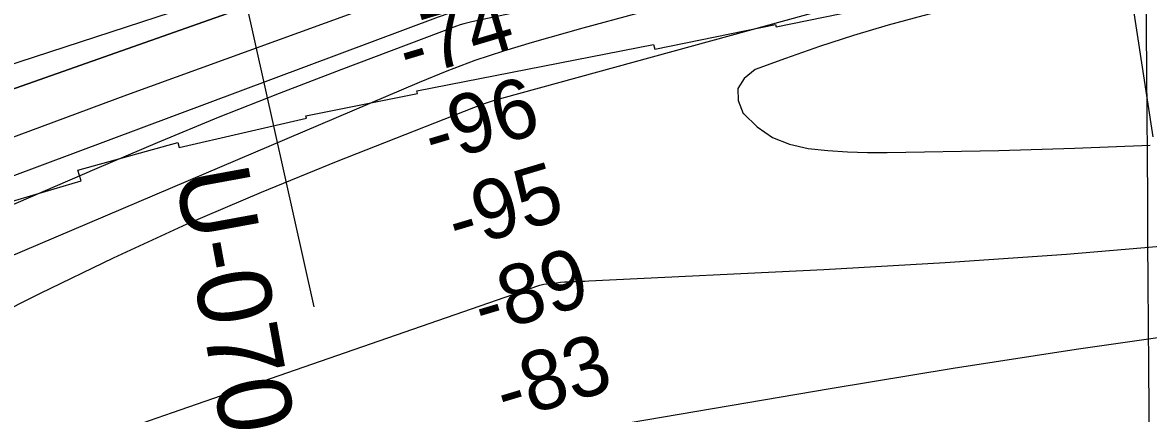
# Model space of a CAD drawing. Extents: x 3508733 to 3546731, y 546897 to 572481.
# Drawn here: x 3516840 to 3518107, y 565110 to 565549 of the extents above; entities that cross this region are included whole.
import ezdxf

# ---------------------------------------------------------------- set-up
doc = ezdxf.new("R2010")
doc.units = 0
for name, color, linetype in [('V-CHAN-NAID', 7, 'Continuous'), ('V-GRID-MAJR', 7, 'Continuous'), ('V-RIVR-RANG', 7, 'Continuous'), ('V-RIVR-RANG-IDEN', 7, 'Continuous'), ('V-RRAP-RVMT', 7, 'Continuous'), ('V-TOPO-DPTH', 7, 'Continuous'), ('V-TOPO-MAJR', 7, 'Continuous'), ('V-TOPO-MINR', 7, 'Continuous')]:
    doc.layers.add(name, color=color, linetype=linetype)

msp = doc.modelspace()

# ---------------------------------------------------------------- linework, layer by layer
at = {"layer": 'V-GRID-MAJR'}
msp.add_spline([(3518190.879, 552332.11), (3518151.221, 558391.11), (3518111.551, 564452.0430000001), (3518071.881, 570512.993), (3518071.8680000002, 570514.91)], degree=3, dxfattribs=at)
at = {"layer": 'V-RIVR-RANG'}
for p, q in [((3517971.68, 566330.2852), (3518111.514, 565420.9742)), ((3516975.6473, 566088.6846999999), (3517167.2507, 565229.797))]:
    msp.add_line(p, q, dxfattribs=at)
at = {"layer": 'V-RRAP-RVMT'}
msp.add_lwpolyline([(3516793.5560000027, 565338.3850000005), (3516905.4190000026, 565371.5210000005), (3516901.7340000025, 565383.6640000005), (3517014.2890000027, 565414.4800000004), (3517015.6620000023, 565408.8910000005), (3517159.1540000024, 565441.9540000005), (3517158.5010000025, 565444.4560000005), (3517284.1880000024, 565469.7160000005), (3517283.4300000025, 565472.6210000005), (3517549.7740000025, 565524.6950000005), (3517551.1010000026, 565519.6100000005), (3517687.0100000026, 565547.1750000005), (3517687.6420000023, 565544.7540000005), (3517830.8750000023, 565573.8730000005), (3517828.7590000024, 565584.6120000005), (3517965.9410000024, 565611.9040000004), (3517966.721000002, 565608.9180000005), (3518119.8880000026, 565637.1650000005)], dxfattribs=at)
at = {"layer": 'V-TOPO-DPTH'}
for points in [[(3518423.3886862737, 565898.4655466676), (3517326.2683833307, 565662.5643742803), (3517315.0726943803, 565659.9749688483), (3517303.9387676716, 565657.1565487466), (3517292.897484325, 565653.9946066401), (3517281.91796322, 565650.603649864), (3516680.8731781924, 565454.7229584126), (3516555.292542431, 565412.9760251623), (3516430.053385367, 565370.2471805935), (3516305.3264463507, 565326.0454690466), (3516180.9409860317, 565280.8618461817), (3515954.5417875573, 565197.1078883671)], [(3518423.3886862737, 565898.4655466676), (3517326.2683833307, 565662.5643742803), (3517315.0726943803, 565659.9749688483), (3517303.9387676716, 565657.1565487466), (3517292.897484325, 565653.9946066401), (3517281.91796322, 565650.603649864), (3516680.8731781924, 565454.7229584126), (3516555.292542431, 565412.9760251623), (3516430.053385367, 565370.2471805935), (3516305.3264463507, 565326.0454690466), (3516180.9409860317, 565280.8618461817), (3515954.5417875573, 565197.1078883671)], [(3516020.597329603, 565168.5781756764), (3516214.642179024, 565246.039114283), (3516345.2495015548, 565297.2481624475), (3516476.2609516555, 565347.3813581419), (3516607.8785931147, 565395.9007751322), (3516739.9003621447, 565443.3443396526), (3517300.234009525, 565640.827400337), (3517304.1311932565, 565642.1149917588), (3517308.0574766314, 565643.2986838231), (3517312.0274094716, 565644.3265268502), (3517316.026441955, 565645.2504705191), (3517552.7533658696, 565695.0420862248), (3517675.1897890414, 565720.5274360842), (3517797.6955763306, 565745.6712054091), (3517920.305409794, 565770.3026039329), (3518042.9846073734, 565794.5924219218), (3518521.9977452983, 565888.3943130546)], [(3516020.597329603, 565168.5781756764), (3516214.642179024, 565246.039114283), (3516345.2495015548, 565297.2481624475), (3516476.2609516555, 565347.3813581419), (3516607.8785931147, 565395.9007751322), (3516739.9003621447, 565443.3443396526), (3517300.234009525, 565640.827400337), (3517304.1311932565, 565642.1149917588), (3517308.0574766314, 565643.2986838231), (3517312.0274094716, 565644.3265268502), (3517316.026441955, 565645.2504705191), (3517552.7533658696, 565695.0420862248), (3517675.1897890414, 565720.5274360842), (3517797.6955763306, 565745.6712054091), (3517920.305409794, 565770.3026039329), (3518042.9846073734, 565794.5924219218), (3518521.9977452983, 565888.3943130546)]]:
    msp.add_lwpolyline(points, dxfattribs=at)
at = {"layer": 'V-TOPO-MAJR'}
for points in [[(3518553.5220918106, 565865.3335647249), (3517807.889502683, 565717.746025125), (3517726.1142726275, 565700.7600775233), (3517644.574071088, 565682.7552743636), (3517563.386412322, 565663.2221878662), (3517482.4337820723, 565642.670245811), (3517381.627259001, 565616.0675730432), (3517351.3819077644, 565607.6444852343), (3517321.3064020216, 565598.6787044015), (3517291.485664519, 565588.8988840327), (3517261.8347725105, 565578.5763706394), (3516956.693556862, 565467.672900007), (3516792.6287252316, 565407.1288088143), (3516628.9730369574, 565345.5139813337), (3516465.9310637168, 565282.2930494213), (3516303.2982338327, 565218.0013812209), (3515989.9224166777, 565092.3334067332)], [(3518255.678024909, 565662.1474238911), (3517852.663415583, 565557.2002066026), (3517813.638594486, 565546.4485864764), (3517774.8395608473, 565534.9714146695), (3517736.3792083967, 565522.4059153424), (3517698.1446434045, 565509.114864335), (3517664.016164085, 565496.7095034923), (3517651.65868368, 565486.7484250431), (3517644.4559823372, 565475.3992052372), (3517644.985449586, 565461.9677733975), (3517650.669695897, 565447.1482002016), (3517650.705076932, 565447.1058560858), (3517666.295303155, 565432.351639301), (3517683.399355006, 565420.4013632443), (3517702.7741452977, 565412.6569982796), (3517723.662761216, 565407.7165740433), (3517745.8536092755, 565405.5949971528), (3517768.0733561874, 565404.0673707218), (3517790.3364513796, 565403.4306699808), (3517812.628445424, 565403.3879196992), (3517938.3075203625, 565405.6654715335), (3518023.4167209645, 565408.062651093), (3518108.4671955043, 565411.5974819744)]]:
    msp.add_lwpolyline(points, dxfattribs=at)
at = {"layer": 'V-TOPO-MINR'}
for points in [[(3518423.3886862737, 565898.4655466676), (3517326.2683833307, 565662.5643742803), (3517315.0726943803, 565659.9749688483), (3517303.9387676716, 565657.1565487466), (3517292.897484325, 565653.9946066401), (3517281.91796322, 565650.603649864), (3516680.8731781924, 565454.7229584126), (3516555.292542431, 565412.9760251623), (3516430.053385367, 565370.2471805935), (3516305.3264463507, 565326.0454690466), (3516180.9409860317, 565280.8618461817), (3515954.5417875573, 565197.1078883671)], [(3518521.9977452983, 565888.3943130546), (3518042.9846073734, 565794.5924219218), (3517920.305409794, 565770.3026039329), (3517797.6955763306, 565745.6712054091), (3517675.1897890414, 565720.5274360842), (3517552.7533658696, 565695.0420862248), (3517316.026441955, 565645.2504705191), (3517312.0274094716, 565644.3265268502), (3517308.0574766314, 565643.2986838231), (3517304.1311932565, 565642.1149917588), (3517300.234009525, 565640.827400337), (3516739.9003621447, 565443.3443396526), (3516607.8785931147, 565395.9007751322), (3516476.2609516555, 565347.3813581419), (3516345.2495015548, 565297.2481624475), (3516214.642179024, 565246.039114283), (3516020.597329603, 565168.5781756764)], [(3518554.211377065, 565773.7671758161), (3517716.0599933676, 565602.6169782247), (3517654.1485596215, 565589.2711684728), (3517592.4534405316, 565575.0325335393), (3517531.082793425, 565559.4546608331), (3517469.9284609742, 565542.9839629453), (3517412.9906002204, 565526.9822562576), (3517380.6835086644, 565517.2279921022), (3517348.663294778, 565506.6577729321), (3517317.0733973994, 565494.8636212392), (3517285.770377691, 565482.2535145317), (3516727.543764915, 565244.7891073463), (3516613.3371090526, 565195.265875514), (3516499.606702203, 565144.6914197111), (3516386.590668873, 565092.5401279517)], [(3518259.143095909, 565768.6330786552), (3517356.58948118, 565570.0666151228), (3517344.073795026, 565567.0343424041), (3517331.6606823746, 565563.6544926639), (3517319.4014299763, 565559.7532773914), (3517307.2447510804, 565555.5044850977), (3516712.825123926, 565333.5435234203), (3516592.849757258, 565287.6849721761), (3516473.368662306, 565240.6000235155), (3516354.6289749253, 565191.6754787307), (3516236.3835592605, 565141.52453653), (3516054.740488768, 565062.8244124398)], [(3518120.368339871, 565713.1374264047), (3517963.354369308, 565681.0414941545), (3517806.464499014, 565648.3443319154), (3517649.657362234, 565615.2463496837), (3517344.9899708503, 565550.3290565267), (3517340.607122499, 565549.2916166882), (3517336.262150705, 565548.1248109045), (3517331.9739937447, 565546.7639562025), (3517327.7237133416, 565545.2737355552), (3517197.5542965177, 565496.32000108), (3517128.4474091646, 565469.7611248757), (3517059.606475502, 565442.5434856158), (3516991.1644723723, 565414.3377017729), (3516922.9884229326, 565385.4731548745), (3516030.5467072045, 565000.030060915)], [(3518174.751859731, 565670.405337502), (3518029.5205738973, 565637.1781983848), (3517884.960038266, 565601.1445932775), (3517740.8466694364, 565563.2400108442), (3517378.398673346, 565464.1461981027), (3517370.461237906, 565461.8379112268), (3517362.5797542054, 565459.3611236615), (3517354.782198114, 565456.631585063), (3517347.0405937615, 565453.7335457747), (3517192.599616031, 565393.0623101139), (3517108.177252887, 565358.5844950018), (3517024.417341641, 565322.6191828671), (3516941.6511082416, 565284.4226251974), (3516859.54732674, 565244.7385705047), (3516753.1482534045, 565191.5410225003), (3516709.17180821, 565168.731315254), (3516665.6763604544, 565145.0679224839), (3516622.9024088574, 565120.1240014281), (3516580.6094547, 565094.3263948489)], [(3517503.364334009, 565096.6264005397), (3517748.332847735, 565138.2368266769), (3517886.795053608, 565160.8861087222), (3518025.4257283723, 565182.4044744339), (3518164.309106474, 565202.2264656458), (3518303.360953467, 565220.9175405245), (3518607.209733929, 565259.8708307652), (3518638.963134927, 565264.0155850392), (3518670.7033539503, 565268.2572861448), (3518702.4238000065, 565272.6444074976), (3518734.131064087, 565277.1284756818), (3519032.0832550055, 565319.9617715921), (3519156.3414444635, 565337.3917686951), (3519280.6745380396, 565354.2549557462)], [(3516870.2270689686, 565063.0946616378), (3517008.407866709, 565111.1959671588), (3517146.6330632, 565159.170011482), (3517420.4228230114, 565253.9827734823), (3517421.796962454, 565254.4089903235), (3517424.593872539, 565255.0488510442), (3517426.01664318, 565255.2624949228), (3517440.507358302, 565256.9573857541), (3517445.052686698, 565257.4287888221), (3517449.603814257, 565257.8206823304), (3517454.1636405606, 565258.0933114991), (3517458.729266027, 565258.286431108), (3517463.2987341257, 565258.4330460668), (3517467.867517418, 565258.597289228), (3517472.4352735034, 565258.7879746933), (3517477.002344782, 565258.996288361), (3517741.286497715, 565271.8174148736), (3517877.907095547, 565279.5978532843), (3518014.4103885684, 565288.9084079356), (3518150.7377243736, 565300.5141369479)]]:
    msp.add_lwpolyline(points, dxfattribs=at)

# ---------------------------------------------------------------- texts
at = {"layer": 'V-CHAN-NAID'}
msp.add_text('CARGILL-NAGOC OILSEED ', height=100.00000199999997, rotation=286.0935022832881, dxfattribs=at).set_placement((3516680.666668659, 565212.5376525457))
at = {"layer": 'V-RIVR-RANG'}
for s, p in [('-74', (3517273.0178424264, 565485.182324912)), ('-96', (3517301.6835640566, 565389.3798988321)), ('-95', (3517328.580234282, 565293.047455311)), ('-89', (3517357.752399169, 565197.3961770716)), ('-83', (3517382.880017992, 565100.5347161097))]:
    msp.add_text(s, height=67.00000000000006, rotation=16.648777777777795, dxfattribs=at).set_placement(p)
at = {"layer": 'V-RIVR-RANG-IDEN'}
msp.add_text('U-070', height=82.999998, rotation=280.3839727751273, dxfattribs=at).set_placement((3517010.8126683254, 565379.6016190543))

doc.saveas('drawing.dxf')
